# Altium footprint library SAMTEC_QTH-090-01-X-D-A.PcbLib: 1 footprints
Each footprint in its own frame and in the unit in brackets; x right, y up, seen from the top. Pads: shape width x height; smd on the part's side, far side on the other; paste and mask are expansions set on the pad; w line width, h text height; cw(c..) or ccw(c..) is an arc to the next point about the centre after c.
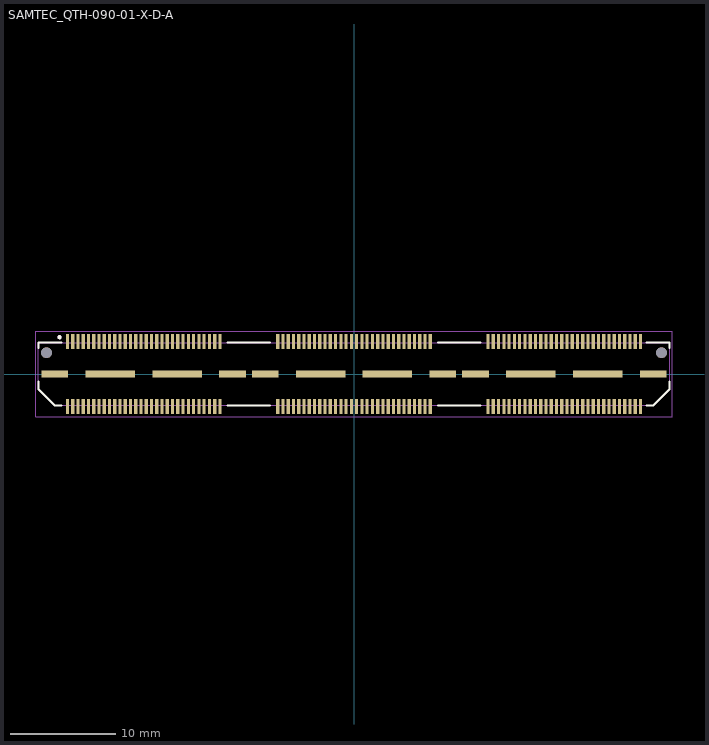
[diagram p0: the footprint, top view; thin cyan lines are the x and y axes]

## SAMTEC_QTH-090-01-X-D-A [mm]
pads (194):
  rect 0.305x1.45 smd: 01(-27.25,3.086) 02(-27.25,-3.086) 03(-26.75,3.086) 04(-26.75,-3.086) 05(-26.25,3.086) 06(-26.25,-3.086) 07(-25.75,3.086) 08(-25.75,-3.086) 09(-25.25,3.086) 10(-25.25,-3.086) 11(-24.75,3.086) 12(-24.75,-3.086) 13(-24.25,3.086) 14(-24.25,-3.086) 15(-23.75,3.086) 16(-23.75,-3.086) 17(-23.25,3.086) 18(-23.25,-3.086) 19(-22.75,3.086) 20(-22.75,-3.086) 21(-22.25,3.086) 22(-22.25,-3.086) 23(-21.75,3.086) 24(-21.75,-3.086) 25(-21.25,3.086) 26(-21.25,-3.086) 27(-20.75,3.086) 28(-20.75,-3.086) 29(-20.25,3.086) 30(-20.25,-3.086) 31(-19.75,3.086) 32(-19.75,-3.086) 33(-19.25,3.086) 34(-19.25,-3.086) 35(-18.75,3.086) 36(-18.75,-3.086) 37(-18.25,3.086) 38(-18.25,-3.086) 39(-17.75,3.086) 40(-17.75,-3.086) 41(-17.25,3.086) 42(-17.25,-3.086) 43(-16.75,3.086) 44(-16.75,-3.086) 45(-16.25,3.086) 46(-16.25,-3.086) 47(-15.75,3.086) 48(-15.75,-3.086) 49(-15.25,3.086) 50(-15.25,-3.086) 51(-14.75,3.086) 52(-14.75,-3.086) 53(-14.25,3.086) 54(-14.25,-3.086) 55(-13.75,3.086) 56(-13.75,-3.086) 57(-13.25,3.086) 58(-13.25,-3.086) 59(-12.75,3.086) 60(-12.75,-3.086) 61(-7.25,3.086) 62(-7.25,-3.086) 63(-6.75,3.086) 64(-6.75,-3.086) 65(-6.25,3.086) 66(-6.25,-3.086) 67(-5.75,3.086) 68(-5.75,-3.086) 69(-5.25,3.086) 70(-5.25,-3.086) 71(-4.75,3.086) 72(-4.75,-3.086) 73(-4.25,3.086) 74(-4.25,-3.086) 75(-3.75,3.086) 76(-3.75,-3.086) 77(-3.25,3.086) 78(-3.25,-3.086) 79(-2.75,3.086) 80(-2.75,-3.086) 81(-2.25,3.086) 82(-2.25,-3.086) 83(-1.75,3.086) 84(-1.75,-3.086) 85(-1.25,3.086) 86(-1.25,-3.086) 87(-0.75,3.086) 88(-0.75,-3.086) 89(-0.25,3.086) 90(-0.25,-3.086) 91(0.25,3.086) 92(0.25,-3.086) 93(0.75,3.086) 94(0.75,-3.086) 95(1.25,3.086) 96(1.25,-3.086) 97(1.75,3.086) 98(1.75,-3.086) 99(2.25,3.086) 100(2.25,-3.086) 101(2.75,3.086) 102(2.75,-3.086) 103(3.25,3.086) 104(3.25,-3.086) 105(3.75,3.086) 106(3.75,-3.086) 107(4.25,3.086) 108(4.25,-3.086) 109(4.75,3.086) 110(4.75,-3.086) 111(5.25,3.086) 112(5.25,-3.086) 113(5.75,3.086) 114(5.75,-3.086) 115(6.25,3.086) 116(6.25,-3.086) 117(6.75,3.086) 118(6.75,-3.086) 119(7.25,3.086) 120(7.25,-3.086) 121(12.75,3.086) 122(12.75,-3.086) 123(13.25,3.086) 124(13.25,-3.086) 125(13.75,3.086) 126(13.75,-3.086) 127(14.25,3.086) 128(14.25,-3.086) 129(14.75,3.086) 130(14.75,-3.086) 131(15.25,3.086) 132(15.25,-3.086) 133(15.75,3.086) 134(15.75,-3.086) 135(16.25,3.086) 136(16.25,-3.086) 137(16.75,3.086) 138(16.75,-3.086) 139(17.25,3.086) 140(17.25,-3.086) 141(17.75,3.086) 142(17.75,-3.086) 143(18.25,3.086) 144(18.25,-3.086) 145(18.75,3.086) 146(18.75,-3.086) 147(19.25,3.086) 148(19.25,-3.086) 149(19.75,3.086) 150(19.75,-3.086) 151(20.25,3.086) 152(20.25,-3.086) 153(20.75,3.086) 154(20.75,-3.086) 155(21.25,3.086) 156(21.25,-3.086) 157(21.75,3.086) 158(21.75,-3.086) 159(22.25,3.086) 160(22.25,-3.086) 161(22.75,3.086) 162(22.75,-3.086) 163(23.25,3.086) 164(23.25,-3.086) 165(23.75,3.086) 166(23.75,-3.086) 167(24.25,3.086) 168(24.25,-3.086) 169(24.75,3.086) 170(24.75,-3.086) 171(25.25,3.086) 172(25.25,-3.086) 173(25.75,3.086) 174(25.75,-3.086) 175(26.25,3.086) 176(26.25,-3.086) 177(26.75,3.086) 178(26.75,-3.086) 179(27.25,3.086) 180(27.25,-3.086)
  rect 2.54x0.64 smd: G1(-28.445,0) G4(-11.555,0) G5(-8.445,0) G8(8.445,0) G9(11.555,0) G12(28.445,0)
  rect 4.7x0.64 smd: G2(-23.175,0) G3(-16.825,0) G6(-3.175,0) G7(3.175,0) G10(16.825,0) G11(23.175,0)
  round 1.02 hole 1.02 unplated: ""(-29.24,2.03) ""(29.24,2.03)
Top Overlay:
  circle w0.2: c-28,3.5 r0.1
  lines w0.2: -30.005,-0.7 -30.005,-1.461 -28.476,-2.985 -27.8,-2.985 ; -30.005,2.5 -30.005,2.985 -27.8,2.985 ; -12,-2.985 -8,-2.985 ; -12,2.985 -8,2.985 ; 8,-2.985 12,-2.985 ; 8,2.985 12,2.985 ; 27.8,-2.985 28.476,-2.985 30.005,-1.461 30.005,-0.7 ; 27.8,2.985 30.005,2.985 30.005,2.5
Mechanical 13:
  circle w0.2: c-28,3.5 r0.1
  lines w0.1: -30.005,-1.461 -30.005,2.985 30.005,2.985 30.005,-1.461 28.476,-2.985 -28.476,-2.985 -30.005,-1.461
Mechanical 15:
  lines w0.05: -30.255,-4.061 -30.255,4.061 30.255,4.061 30.255,-4.061 -30.255,-4.061
3D body "strip_qth-090-01-f-d-a.stp": height 4.06, standoff -0.97, extent -30.01,-3.555 30.01,3.555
